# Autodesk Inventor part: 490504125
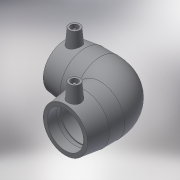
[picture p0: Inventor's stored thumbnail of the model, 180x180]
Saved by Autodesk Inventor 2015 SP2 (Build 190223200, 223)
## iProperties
Created: 2017-06
Part Number: 490504125
Material: Generic
Description: PLASSON 90° ELBOW 125
Document SubType Name: Modeling
Designer: KIM
Mass: 55.0731 g
Surface Area: 148.067 cm^2
Volume: 55.0731 cm^3
Density: 1 g/cm^3
Appearance: Default
Author: KIM
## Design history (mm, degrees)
derived "490504.ipt"
feature "Solid1::490504.ipt"
tag "TaggingFeature1"
body "Solid1"
other parameters: "d2" = 165, "d4" = 67.75, "d5" = 148.5, "d8" = 168 deg, "d11" = 13.33333, "d14" = 17.6296, "d18" = 125, "d19" = 3.52592, "d20" = 168 deg, "d22" = 151.8, "d23" = 165, "d24" = 147.246, "d29" = 89, "d30" = 15, "d31" = 94.85, "d34" = 5 deg, "d35" = 15, "d39" = 5 deg, "d41" = 4, "d42" = 14, "d43" = 0, "d45" = 4, "d46" = 14, "d47" = 0, "d49" = 125, "d50" = 106.25, "d54" = 90 deg, "d65" = 125, "d67" = 45 deg, "d71" = 90 deg, "d75" = 8.25, "d82" = 45 deg, "d84" = 148.5, "d86" = 74.25, "d87" = 90 deg, "d91" = 0, "d93" = 0, "d94" = 90 deg, "d95" = 75.9, "d98" = 271, "d101" = 3, "d102" = 0, "d103" = 3, "d104" = 0, "d105" = 29, "d106" = 7.25, "d107" = 271, "d110" = 55, "d_" = 125, "L_" = 271, "D_" = 165, "A_" = 89, "d_2" = 12
